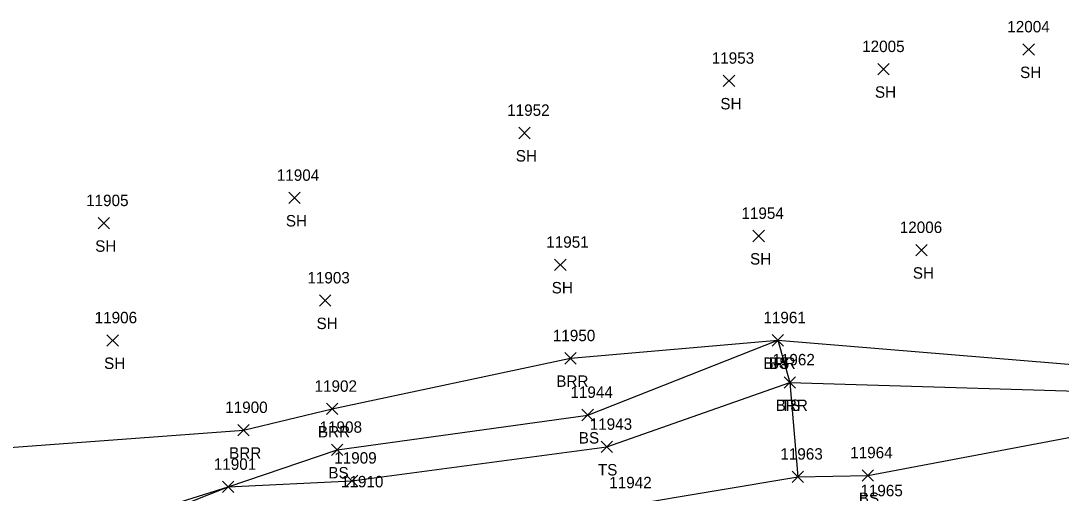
# Model space of a CAD drawing. Extents: x 1475671 to 1477951, y 592661 to 593821.
# Drawn here: x 1477263.9 to 1477446.2, y 593725.6 to 593808.3 of the extents above; entities that cross this region are included whole.
import ezdxf

# ---------------------------------------------------------------- set-up
doc = ezdxf.new("R2010")
doc.units = 0
for name, color, linetype in [('L_A', 7, 'Continuous'), ('L_I', 7, 'Continuous'), ('L_TIC', 7, 'Continuous'), ('LABL', 7, 'Continuous'), ('LELB', 7, 'Continuous'), ('M_I', 7, 'Continuous')]:
    doc.layers.add(name, color=color, linetype=linetype)

msp = doc.modelspace()

# ---------------------------------------------------------------- linework, layer by layer
at = {"layer": 'L_TIC'}
for points in [[(1477439.5, 593802.31), (1477441.5, 593804.31)], [(1477441.5, 593802.31), (1477439.5, 593804.31)], [(1477414.07, 593798.86), (1477416.07, 593800.86)], [(1477416.07, 593798.86), (1477414.07, 593800.86)], [(1477386.99, 593796.82), (1477388.99, 593798.82)], [(1477388.99, 593796.82), (1477386.99, 593798.82)], [(1477351.15, 593787.69), (1477353.15, 593789.69)], [(1477353.15, 593787.69), (1477351.15, 593789.69)], [(1477310.87, 593776.31), (1477312.87, 593778.31)], [(1477312.87, 593776.31), (1477310.87, 593778.31)], [(1477277.47, 593771.88), (1477279.47, 593773.88)], [(1477279.47, 593771.88), (1477277.47, 593773.88)], [(1477392.19, 593769.64), (1477394.19, 593771.64)], [(1477394.19, 593769.64), (1477392.19, 593771.64)], [(1477420.71, 593767.17), (1477422.71, 593769.17)], [(1477422.71, 593767.17), (1477420.71, 593769.17)], [(1477357.44, 593764.59), (1477359.44, 593766.59)], [(1477359.44, 593764.59), (1477357.44, 593766.59)], [(1477316.24, 593758.34), (1477318.24, 593760.34)], [(1477318.24, 593758.34), (1477316.24, 593760.34)], [(1477279.02, 593751.36), (1477281.02, 593753.36)], [(1477281.02, 593751.36), (1477279.02, 593753.36)], [(1477395.53, 593751.37), (1477397.53, 593753.37)], [(1477397.53, 593751.37), (1477395.53, 593753.37)], [(1477395.53, 593751.37), (1477397.53, 593753.37)], [(1477397.53, 593751.37), (1477395.53, 593753.37)], [(1477359.24, 593748.22), (1477361.24, 593750.22)], [(1477361.24, 593748.22), (1477359.24, 593750.22)], [(1477397.67, 593743.99), (1477399.67, 593745.99)], [(1477399.67, 593743.99), (1477397.67, 593745.99)], [(1477397.67, 593743.99), (1477399.67, 593745.99)], [(1477399.67, 593743.99), (1477397.67, 593745.99)], [(1477317.48, 593739.36), (1477319.48, 593741.36)], [(1477319.48, 593739.36), (1477317.48, 593741.36)], [(1477362.24, 593738.29), (1477364.24, 593740.29)], [(1477364.24, 593738.29), (1477362.24, 593740.29)], [(1477301.92, 593735.64), (1477303.92, 593737.64)], [(1477303.92, 593735.64), (1477301.92, 593737.64)], [(1477318.36, 593732.18), (1477320.36, 593734.18)], [(1477320.36, 593732.18), (1477318.36, 593734.18)], [(1477365.61, 593732.7), (1477367.61, 593734.7)], [(1477367.61, 593732.7), (1477365.61, 593734.7)], [(1477411.3, 593727.71), (1477413.3, 593729.71)], [(1477413.3, 593727.71), (1477411.3, 593729.71)], [(1477320.94, 593726.78), (1477322.94, 593728.78)], [(1477322.94, 593726.78), (1477320.94, 593728.78)], [(1477399.06, 593727.47), (1477401.06, 593729.47)], [(1477401.06, 593727.47), (1477399.06, 593729.47)], [(1477399.06, 593727.47), (1477401.06, 593729.47)], [(1477401.06, 593727.47), (1477399.06, 593729.47)], [(1477399.06, 593727.47), (1477401.06, 593729.47)], [(1477401.06, 593727.47), (1477399.06, 593729.47)], [(1477299.26, 593725.69), (1477301.26, 593727.69)], [(1477301.26, 593725.69), (1477299.26, 593727.69)], [(1477299.26, 593725.69), (1477301.26, 593727.69)], [(1477301.26, 593725.69), (1477299.26, 593727.69)]]:
    msp.add_lwpolyline(points, dxfattribs=at)
at = {"layer": 'LABL'}
for points in [[(1477213.21, 593729.41), (1477259.55, 593733.41), (1477302.92, 593736.64), (1477318.48, 593740.36), (1477360.24, 593749.22), (1477396.53, 593752.37), (1477398.67, 593744.99), (1477400.06, 593728.47)], [(1477070.39, 593692.41), (1477067.99, 593679.34), (1477071.39, 593656.39), (1477069.25, 593632), (1477071.86, 593601.77), (1477082.98, 593597.36), (1477107.11, 593607.76), (1477119.12, 593610.41), (1477150.77, 593620.61), (1477191.19, 593657.06), (1477226.2, 593667.71), (1477230.98, 593680.18), (1477228.88, 593689.92), (1477268.63, 593704.57), (1477322.35, 593715.8), (1477370.03, 593723.46), (1477400.06, 593728.47)]]:
    msp.add_lwpolyline(points, dxfattribs=at)
at = {"layer": 'LELB'}
for points in [[(1477137.36, 593693.23), (1477131.81, 593697.29), (1477156.86, 593699.4), (1477177.34, 593702.04), (1477224.05, 593707.11), (1477269.77, 593714.64), (1477300.26, 593726.69), (1477319.36, 593733.18), (1477363.24, 593739.29), (1477396.53, 593752.37), (1477463.79, 593746.86), (1477493.79, 593749.99), (1477520.39, 593749.88), (1477564.42, 593755.36)], [(1477132.94, 593704.7), (1477159.3, 593706.23), (1477177.13, 593706.7), (1477223.11, 593710.47), (1477269.09, 593716.91), (1477300.26, 593726.69), (1477321.94, 593727.78), (1477366.61, 593733.7), (1477398.67, 593744.99), (1477464.61, 593743.02), (1477494.58, 593745.49), (1477521.06, 593747.41), (1477564.24, 593751.76)], [(1477400.06, 593728.47), (1477412.3, 593728.71), (1477465.19, 593738.68), (1477495.25, 593741.44), (1477521.63, 593743.19), (1477564.19, 593748.99)]]:
    msp.add_lwpolyline(points, dxfattribs=at)

# ---------------------------------------------------------------- texts
at = {"layer": 'L_A'}
for s, p in [('SH', (1477438.99, 593798.31)), ('SH', (1477413.56, 593794.86)), ('SH', (1477386.48, 593792.82)), ('SH', (1477350.64, 593783.69)), ('SH', (1477310.36, 593772.31)), ('SH', (1477276.95, 593767.88)), ('SH', (1477391.68, 593765.64)), ('SH', (1477420.2, 593763.17)), ('SH', (1477356.93, 593760.59)), ('SH', (1477315.73, 593754.34)), ('SH', (1477278.51, 593747.36)), ('BRR', (1477394.02, 593747.37)), ('BS', (1477394.97, 593747.37)), ('BRR', (1477357.73, 593744.22)), ('BRR', (1477396.16, 593739.99)), ('TS', (1477397.08, 593739.99)), ('BRR', (1477315.97, 593735.36)), ('BS', (1477361.68, 593734.29)), ('BRR', (1477300.41, 593731.64)), ('BS', (1477317.8, 593728.18)), ('TS', (1477365.02, 593728.7)), ('BS', (1477410.74, 593723.71))]:
    msp.add_text(s, height=2, dxfattribs=at).set_placement(p)
at = {"layer": 'L_I'}
for s, p in [('12004', (1477436.75, 593806.31)), ('12005', (1477411.32, 593802.86)), ('11953', (1477384.97, 593800.82)), ('11952', (1477349.13, 593791.69)), ('11904', (1477308.77, 593780.31)), ('11905', (1477275.36, 593775.88)), ('11954', (1477390.17, 593773.64)), ('12006', (1477417.91, 593771.17)), ('11951', (1477355.98, 593768.59)), ('11903', (1477314.13, 593762.34)), ('11906', (1477276.86, 593755.36)), ('11961', (1477394.02, 593755.37)), ('11961', (1477394.02, 593755.37)), ('11950', (1477357.13, 593752.22)), ('11962', (1477395.6, 593747.99)), ('11962', (1477395.6, 593747.99)), ('11902', (1477315.38, 593743.36)), ('11944', (1477360.21, 593742.29)), ('11900', (1477299.73, 593739.64)), ('11908', (1477316.26, 593736.18)), ('11943', (1477363.59, 593736.7)), ('11963', (1477396.99, 593731.47)), ('11963', (1477396.99, 593731.47)), ('11963', (1477396.99, 593731.47)), ('11964', (1477409.23, 593731.71)), ('11901', (1477297.73, 593729.69)), ('11901', (1477297.73, 593729.69)), ('11909', (1477318.83, 593730.78)), ('11942', (1477367.01, 593726.46)), ('11965', (1477411.01, 593725.06)), ('11965', (1477411.01, 593725.06))]:
    msp.add_text(s, height=2, dxfattribs=at).set_placement(p)
at = {"layer": 'M_I'}
msp.add_text('11910', height=2, dxfattribs=at).set_placement((1477320.01, 593726.62))

doc.saveas('drawing.dxf')
